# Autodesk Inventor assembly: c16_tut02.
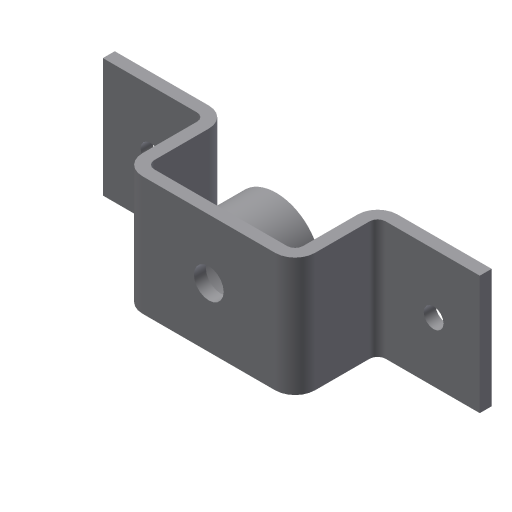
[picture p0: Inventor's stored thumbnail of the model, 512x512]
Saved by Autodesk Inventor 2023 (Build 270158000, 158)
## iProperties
Created: 2010-05
Part Number: c16_tut02.
Document SubType Name: Weldment
Designer: CADSoft
Weld Material: Welded Aluminum-6061
Author: CADSoft
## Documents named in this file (3)
- D:\PROJECTS\Project 2022\Autodesk Inventor For Professional 2023\RESOURCES INVENTOR 2023\RESOURCES INVENTOR 2023\Inventor_2023_tut\Inventor_2023_tut\c16_Inv_2023_tut\c16_Inv_tut_2022\c16_tut02\c16_tut02..iam
- D:\PROJECTS\Project 2022\Autodesk Inventor For Professional 2023\RESOURCES INVENTOR 2023\RESOURCES INVENTOR 2023\Inventor_2023_tut\Inventor_2023_tut\c16_Inv_2023_tut\c16_Inv_tut_2022\c16_tut02\Bracket.ipt
- D:\PROJECTS\Project 2022\Autodesk Inventor For Professional 2023\RESOURCES INVENTOR 2023\RESOURCES INVENTOR 2023\Inventor_2023_tut\Inventor_2023_tut\c16_Inv_2023_tut\c16_Inv_tut_2022\c16_tut02\Cylinder.ipt
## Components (2 placed, 2 different names)
1. Bracket:1 — Mate:1, Mate:2
2. Cylinder:1 — Mate:1, Mate:2
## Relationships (2: Mate 2)
- Mate:1: Bracket:1 ↔ Cylinder:1
- Mate:2: Bracket:1 ↔ Cylinder:1
